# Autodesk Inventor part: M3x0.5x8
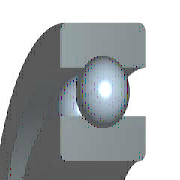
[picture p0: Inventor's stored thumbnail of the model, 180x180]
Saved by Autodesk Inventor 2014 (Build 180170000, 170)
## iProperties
Created: 2009-02
Part Number: M3x0.5x8
Material: 강, 연강
Description: 깊은 그루브 볼 베어링
Document SubType Name: Modeling
Standard: KS B 2023
Designer: KYOUNG IL JANG
Standards Organization: KS
Language: ko-KR
Size Designation: 6202 - 15 x 35 x 11
Categories: <MemberInstance><Categories><Category DisplayName="샤프트 부품" InternalName="7f7aeb1f-a693-4053-b835-cee3144e0d98" Mnemonic="SHFT"><Category DisplayName="베어링" Inter
Density: 7.86 g/cm^3
Mass: 42.4004 g
Surface Area: 51.5584 cm^2
Volume: 5.39445 cm^3
Vendor: CBT Solutions
Appearance: 강철
Company: 한국ATC센터
IsCustomPart: 1
Author: KYOUNG IL JANG
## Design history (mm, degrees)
sketch "스케치" dims "d0" = 5.2 (= -0.26 x WD + 0.26 x BD)
  geometry: L1 (2.9, 12.5)-(8.1, 12.5); L2 (5.5, 12.5)-(5.5, 9.9); L3 (5.5, 12.5)-(5.5, 15.1); L4 (3.568, 10.76)-(0, 10.76); L5 (0, 7.5)-(11, 7.5); L6 (3.568, 14.24)-(0, 14.24); L7 (0, 17.5)-(11, 17.5); L8 (11, 7.5)-(11, 10.76); L9 (7.432, 10.76)-(11, 10.76); L10 (7.432, 14.24)-(11, 14.24); L11 (11, 17.5)-(11, 14.24); L12 (-1.4, 0)-(8.4, 0) reference; L13 (0, -0.3)-(0, 5.3) reference
  constraints: 22 end point, 4 point on line, 2 collinear, 2 perpendicular, 2 symmetric about line, 1 midpoint, 1 parallel, 14 other
  dimensions: "d9" = 15 diameter of L5 L12 (= WD); "d11" = 35 diameter of L7 L12 (= BD); "d12" = 11 distance between parallel lines of L8 L13 (= KB); "d13" = 21.52 diameter of L9 L12 (= 0.326 x BD + 0.674 x WD)
revolve "본체" stored, may be unused: angle "d6" = 90 deg
revolve "볼" stored, may be unused: angle "d7" = 90 deg
pattern_circular "IDS_ARRAYBALL[SIMPL:T]" dims angle "d3" = 360 deg
body "Solid1"
fillet "모깎기1" dims "d1" = 0.6 (= KRS)
other parameters: "WD" = 15 [user parameter; used in 5 equation terms], "BD" = 35 [user parameter; used in 5 equation terms], "KB" = 11 [user parameter; used in 1 equation term], "KRS" = 0.6 [user parameter; used in 1 equation term], "d4" = 0, "d5" = 0, "d8" = 0, "d14" = 0, "d15" = 0, "BBA" = 0 [user parameter], "BC0" = 3750000 [user parameter], "BC" = 7800000 [user parameter], "BR" = 17.5 (= 0.5 x BD) [user parameter], "WR" = 7.5 (= 0.5 x WD) [user parameter]
